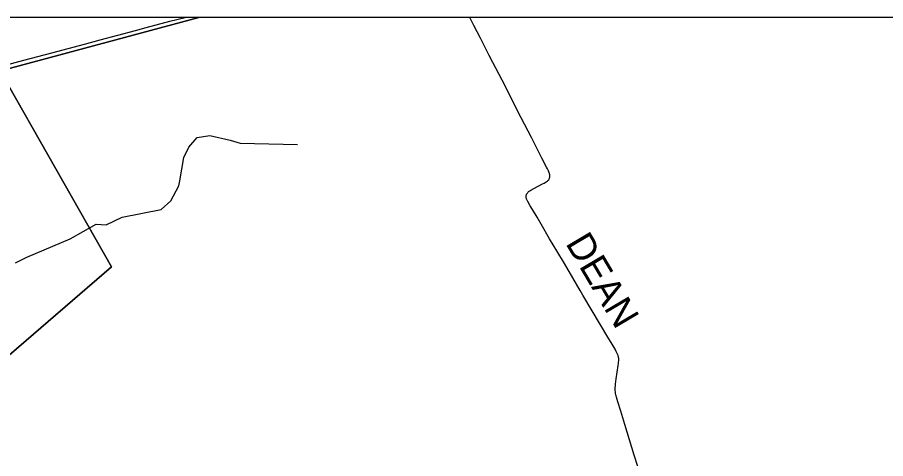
# Model space of a CAD drawing. Extents: x -49 to -8.2, y 9.4 to 23.5.
# Drawn here: x -45.156 to -44.254, y 20.545 to 21.004 of the extents above; entities that cross this region are included whole.
import ezdxf

# ---------------------------------------------------------------- set-up
doc = ezdxf.new("R2010")
doc.units = 0
for name, color, linetype in [('GM_X_Adjacent_County', 7, 'Continuous'), ('GM_X_County_Road', 7, 'Continuous'), ('GM_X_Minor_River', 7, 'Continuous'), ('GM_X_Township', 7, 'Continuous'), ('GM_X_Township_Road', 7, 'Continuous'), ('GM_X_Township_Road_Text', 7, 'Continuous')]:
    doc.layers.add(name, color=color, linetype=linetype)

msp = doc.modelspace()

# ---------------------------------------------------------------- linework, layer by layer
at = {"layer": 'GM_X_Adjacent_County'}
msp.add_lwpolyline([(-42.09891, 21.00392), (-46.28954, 21.00392), (-46.28954, 15.42735)], dxfattribs=at)
at = {"layer": 'GM_X_County_Road'}
for points in [[(-45.0221, 20.99323), (-44.99763, 20.99979), (-44.98173, 21.00392)], [(-45.37021, 20.90179), (-45.3481, 20.90746), (-45.33137, 20.91176), (-45.2956, 20.92111), (-45.27336, 20.92694), (-45.24747, 20.93354), (-45.22393, 20.9396), (-45.18421, 20.95016), (-45.14923, 20.95945), (-45.12011, 20.96714), (-45.08624, 20.97605), (-45.07009, 20.98037), (-45.03334, 20.99023), (-45.0221, 20.99323)]]:
    msp.add_lwpolyline(points, dxfattribs=at)
at = {"layer": 'GM_X_Minor_River'}
msp.add_lwpolyline([(-45.15788, 20.7488), (-45.14622, 20.7547), (-45.10099, 20.77375), (-45.07403, 20.7889), (-45.06361, 20.78818), (-45.04718, 20.79628), (-45.00668, 20.80421), (-44.99668, 20.81316), (-44.9881, 20.82879), (-44.98707, 20.83409), (-44.9831, 20.85813), (-44.978, 20.86906), (-44.96913, 20.87898), (-44.9562, 20.88125), (-44.93486, 20.87618), (-44.92466, 20.87318), (-44.86515, 20.87171)], dxfattribs=at)
at = {"layer": 'GM_X_Township'}
msp.add_line((-42.09891, 21.00392), (-44.96748, 21.00392), dxfattribs=at)
for points in [[(-44.96748, 21.00392), (-46.28954, 21.00392), (-46.28954, 19.72602)], [(-46.28954, 19.72602), (-46.28748, 19.72522), (-46.14563, 19.67369), (-45.97275, 19.61052), (-45.9185, 19.58255), (-45.9046, 19.57576), (-45.39885, 19.9853), (-45.3824, 19.99861), (-45.03769, 20.27755), (-45.26676, 20.56441), (-45.25724, 20.57271), (-45.23832, 20.58923), (-45.05814, 20.74441), (-45.17386, 20.94826), (-45.17205, 20.94872), (-44.96748, 21.00392)], [(-44.96748, 21.00392), (-45.17205, 20.94872), (-45.17386, 20.94826), (-45.05814, 20.74441), (-45.23832, 20.58923), (-45.25724, 20.57271), (-45.26676, 20.56441), (-45.03769, 20.27755), (-45.3824, 19.99861), (-45.37137, 19.99764), (-45.32414, 19.99586), (-45.29569, 19.99479), (-45.26848, 19.99483), (-45.22243, 20.00775), (-45.23544, 19.53179), (-45.23665, 19.48739), (-45.23827, 19.42819)]]:
    msp.add_lwpolyline(points, dxfattribs=at)
at = {"layer": 'GM_X_Township_Road'}
msp.add_lwpolyline([(-44.51165, 20.53694), (-44.5153, 20.54882), (-44.525, 20.58059), (-44.52932, 20.59461), (-44.53224, 20.60406), (-44.53362, 20.60887), (-44.53399, 20.61027), (-44.53428, 20.61152), (-44.53459, 20.61302), (-44.53478, 20.61444), (-44.53491, 20.61592), (-44.53494, 20.61744), (-44.53491, 20.619), (-44.53479, 20.62085), (-44.53462, 20.62262), (-44.53396, 20.62819), (-44.53184, 20.6421), (-44.53157, 20.64406), (-44.53142, 20.64549), (-44.53134, 20.64668), (-44.53132, 20.64779), (-44.53134, 20.64849), (-44.5314, 20.64909), (-44.53155, 20.65012), (-44.53169, 20.65092), (-44.53186, 20.65164), (-44.53206, 20.65236), (-44.53229, 20.65306), (-44.53259, 20.65386), (-44.53283, 20.65443), (-44.53386, 20.65653), (-44.53508, 20.6588), (-44.53827, 20.66414), (-44.54258, 20.67134), (-44.5589, 20.69885), (-44.56849, 20.7152), (-44.57131, 20.72002), (-44.57901, 20.73315), (-44.58782, 20.74815), (-44.59565, 20.7612), (-44.60309, 20.77376), (-44.61186, 20.78878), (-44.61609, 20.79603), (-44.62099, 20.80432), (-44.62327, 20.80803), (-44.62581, 20.81232), (-44.6262, 20.81306), (-44.62653, 20.81368), (-44.62682, 20.81431), (-44.62707, 20.81497), (-44.62725, 20.81563), (-44.62735, 20.81621), (-44.62745, 20.81727), (-44.62744, 20.81819), (-44.62735, 20.81886), (-44.62721, 20.81945), (-44.62705, 20.81992), (-44.62687, 20.82029), (-44.6266, 20.82079), (-44.62624, 20.8213), (-44.62581, 20.82188), (-44.62542, 20.82231), (-44.62495, 20.82274), (-44.6245, 20.82313), (-44.62374, 20.82367), (-44.62269, 20.82433), (-44.61942, 20.82614), (-44.61057, 20.8307), (-44.60892, 20.83157), (-44.60681, 20.83279), (-44.60607, 20.8333), (-44.60549, 20.83375), (-44.60495, 20.83417), (-44.60444, 20.83462), (-44.60403, 20.83509), (-44.6037, 20.83558), (-44.60343, 20.8361), (-44.60323, 20.83659), (-44.6031, 20.83702), (-44.603, 20.83762), (-44.6029, 20.83854), (-44.6029, 20.83937), (-44.60294, 20.83988), (-44.60302, 20.84052), (-44.60313, 20.84105), (-44.60328, 20.84165), (-44.6035, 20.84226), (-44.60393, 20.84339), (-44.60436, 20.84439), (-44.60533, 20.84637), (-44.60632, 20.84831), (-44.61104, 20.85743), (-44.6221, 20.87899), (-44.6326, 20.8996), (-44.65258, 20.93856), (-44.66204, 20.95695), (-44.66584, 20.96442), (-44.675, 20.98242), (-44.68167, 20.9954), (-44.68608, 21.00392)], dxfattribs=at)

# ---------------------------------------------------------------- texts
at = {"layer": 'GM_X_Township_Road_Text'}
msp.add_text('DEAN', height=0.028409, rotation=300.62636, dxfattribs=at).set_placement((-44.58714, 20.76908))

doc.saveas('drawing.dxf')
